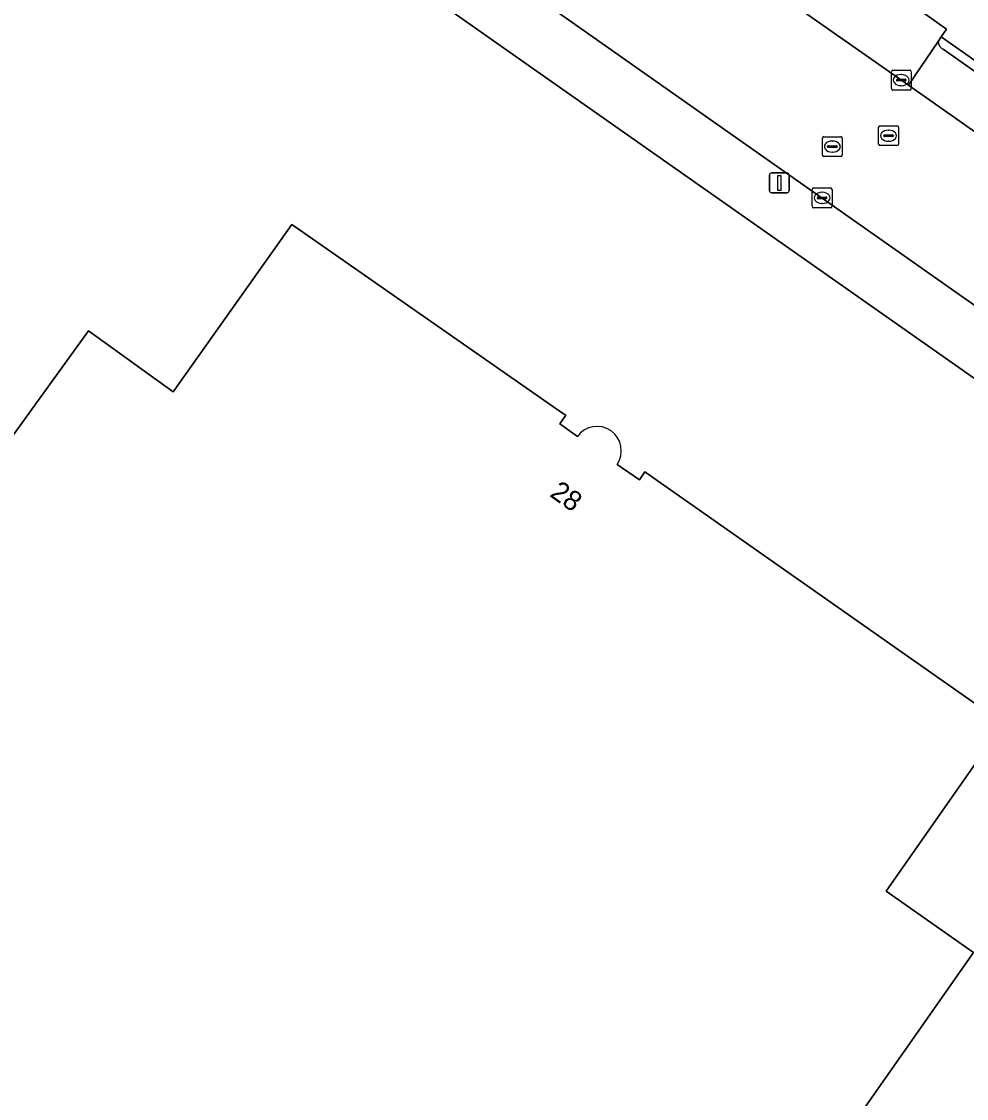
# Model space of a CAD drawing. Extents: x 155018 to 156648, y 383979 to 385733.
# Drawn here: x 155513.9 to 155561.5, y 384893 to 384947.3 of the extents above; entities that cross this region are included whole.
import ezdxf

# ---------------------------------------------------------------- set-up
doc = ezdxf.new("R2010")
doc.units = 0
for name, color, linetype in [('IMGEO_Erf', 7, 'Continuous'), ('IMGEO_Kolk', 7, 'Continuous'), ('IMGEO_Lichtmast', 7, 'Continuous'), ('IMGEO_Pand', 7, 'Continuous'), ('IMGEO_Pand_nummerreeks', 7, 'Continuous'), ('IMGEO_Parkeervlak_open', 7, 'Continuous'), ('IMGEO_Rijbaan_lokaal_gesloten', 7, 'Continuous'), ('IMGEO_Rioolput', 7, 'Continuous'), ('IMGEO_Voetpad_open', 7, 'Continuous')]:
    doc.layers.add(name, color=color, linetype=linetype)

msp = doc.modelspace()

# ---------------------------------------------------------------- linework, layer by layer
at = {"layer": 'IMGEO_Erf'}
for points in [[(155457.525, 385018.63), (155458.619, 385017.864), (155484.145, 385000), (155491.64, 384994.721), (155500, 384988.865), (155510.83, 384981.203), (155511.294, 384981.88), (155516.258, 384978.35), (155515.775, 384977.663), (155553.601, 384951.142), (155553.738, 384951.046), (155554.058, 384951.47), (155560.497, 384946.89), (155560.229, 384946.497), (155580.857, 384931.994), (155586.597, 384927.958), (155607.46, 384913.427), (155617.317, 384906.512), (155620.874, 384904.014), (155651.48, 384882.509)], [(155645.703, 384870.176), (155613.715, 384892.628), (155600.657, 384901.793), (155582.308, 384914.778), (155574.917, 384919.981), (155570.133, 384923.483), (155539.854, 384944.743), (155535.161, 384948.038), (155534.984, 384948.163), (155531.101, 384950.889), (155530.5, 384951.311), (155510.828, 384965.124), (155506.264, 384968.328), (155505.588, 384968.803), (155501.395, 384971.747), (155500, 384972.727), (155492.047, 384978.311), (155491.266, 384978.86), (155482.605, 384984.76), (155482.381, 384984.92), (155460.927, 385000), (155450.653, 385007.222)], [(155500, 384877.008), (155485.234, 384887.357), (155500, 384907.81), (155514.306, 384927.626), (155517.232, 384931.679), (155521.497, 384928.598), (155527.474, 384937.038), (155541.136, 384927.524), (155541.289, 384927.418), (155540.987, 384926.985), (155541.878, 384926.35)], [(155543.877, 384924.937), (155545.004, 384924.158), (155545.287, 384924.561), (155563.372, 384911.879), (155557.442, 384903.43), (155561.847, 384900.331), (155558.976, 384896.238), (155532.714, 384858.794), (155540.579, 384853.259), (155545.535, 384849.771), (155571.761, 384887.2), (155574.63, 384891.294), (155591.828, 384879.262), (155575.198, 384855.542), (155560.868, 384835.103), (155560.52, 384834.638), (155543.355, 384846.66), (155543.923, 384847.471), (155538.96, 384850.949), (155531.075, 384856.475), (155530.489, 384855.639), (155507.887, 384871.48), (155500, 384877.008)]]:
    msp.add_lwpolyline(points, dxfattribs=at)
msp.add_arc((155542.869, 384925.631), 1.224, 325.4515, 144.0391, dxfattribs=at)
at = {"layer": 'IMGEO_Kolk'}
for p, q in [((155557.784, 384944.814), (155558.636, 384944.814)), ((155557.709, 384943.888), (155557.709, 384944.74)), ((155557.968, 384944.308), (155557.968, 384944.32)), ((155558.406, 384944.271), (155558.008, 384944.271)), ((155558.011, 384944.357), (155558.409, 384944.357)), ((155558.197, 384944.594), (155558.222, 384944.594)), ((155558.452, 384944.32), (155558.452, 384944.308)), ((155558.71, 384944.74), (155558.71, 384943.888)), ((155558.636, 384943.814), (155557.784, 384943.814)), ((155558.22, 384944.034), (155558.195, 384944.034)), ((155553.716, 384937.952), (155553.716, 384938.804)), ((155553.791, 384938.878), (155554.643, 384938.878)), ((155554.717, 384938.804), (155554.717, 384937.952)), ((155553.975, 384938.372), (155553.975, 384938.384)), ((155554.413, 384938.335), (155554.015, 384938.335)), ((155554.018, 384938.421), (155554.416, 384938.421)), ((155554.204, 384938.658), (155554.229, 384938.658)), ((155554.459, 384938.384), (155554.459, 384938.372)), ((155554.643, 384937.878), (155553.791, 384937.878)), ((155554.227, 384938.098), (155554.202, 384938.098))]:
    msp.add_line(p, q, dxfattribs=at)
for points in [[(155557.784, 384944.814), (155558.636, 384944.814)], [(155557.709, 384943.888), (155557.709, 384944.74)], [(155558.71, 384944.74), (155558.71, 384943.888)], [(155558.636, 384943.814), (155557.784, 384943.814)], [(155553.716, 384937.952), (155553.716, 384938.804)], [(155553.791, 384938.878), (155554.643, 384938.878)], [(155554.717, 384938.804), (155554.717, 384937.952)], [(155554.643, 384937.878), (155553.791, 384937.878)]]:
    msp.add_lwpolyline(points, dxfattribs=at)
for centre, radius, start, end in [((155557.786, 384944.738), 0.0765, 91.552, 178.448), ((155557.786, 384944.738), 0.0765, 91.552, 178.448), ((155558.634, 384944.738), 0.0765, 1.552, 88.448), ((155558.634, 384944.738), 0.0765, 1.552, 88.448), ((155558.008, 384944.317), 0.0403, 85.8775, 175.7526), ((155558.005, 384944.307), 0.0366, 178.938, 274.7102), ((155558.409, 384944.314), 0.043, 264.8664, 352.4533), ((155558.413, 384944.319), 0.0386, 1.7309, 96.639), ((155557.786, 384943.89), 0.0765, 181.552, 268.448), ((155557.786, 384943.89), 0.0765, 181.552, 268.448), ((155558.634, 384943.89), 0.0765, 271.552, 358.448), ((155558.634, 384943.89), 0.0765, 271.552, 358.448), ((155553.793, 384938.802), 0.0765, 91.552, 178.448), ((155553.793, 384938.802), 0.0765, 91.552, 178.448), ((155554.641, 384938.802), 0.0765, 1.552, 88.448), ((155554.641, 384938.802), 0.0765, 1.552, 88.448), ((155554.015, 384938.381), 0.0403, 85.8775, 175.7526), ((155554.012, 384938.371), 0.0366, 178.938, 274.7102), ((155554.416, 384938.378), 0.043, 264.8664, 352.4533), ((155554.42, 384938.383), 0.0386, 1.7309, 96.639), ((155553.793, 384937.954), 0.0765, 181.552, 268.448), ((155553.793, 384937.954), 0.0765, 181.552, 268.448), ((155554.641, 384937.954), 0.0765, 271.552, 358.448), ((155554.641, 384937.954), 0.0765, 271.552, 358.448)]:
    msp.add_arc(centre, radius, start, end, dxfattribs=at)
for centre, major_axis, ratio, start_param, end_param in [((155558.196, 384944.314), (-0.387, 0.002), 0.722429, 4.712389, 7.853982), ((155558.221, 384944.314), (-0.39, 0.002), 0.717154, 1.570796, 4.712389), ((155554.203, 384938.378), (-0.387, 0.002), 0.722429, 4.712389, 7.853982), ((155554.228, 384938.378), (-0.39, 0.002), 0.717154, 1.570796, 4.712389)]:
    msp.add_ellipse(centre, major_axis=major_axis, ratio=ratio, start_param=start_param, end_param=end_param, dxfattribs=at)
at = {"layer": 'IMGEO_Lichtmast'}
for p, q in [((155551.565, 384938.732), (155551.565, 384939.532)), ((155551.565, 384939.532), (155551.565, 384938.732)), ((155551.665, 384939.632), (155552.455, 384939.632)), ((155552.455, 384939.632), (155551.665, 384939.632)), ((155552.555, 384939.532), (155552.555, 384938.732)), ((155552.555, 384938.732), (155552.555, 384939.532)), ((155552.455, 384938.632), (155551.665, 384938.632)), ((155551.665, 384938.632), (155552.455, 384938.632))]:
    msp.add_line(p, q, dxfattribs=at)
msp.add_lwpolyline([(155551.985, 384939.507), (155552.135, 384939.507), (155552.135, 384938.757), (155551.985, 384938.757), (155551.985, 384939.507)], dxfattribs=at)
for centre, start, end in [((155551.665, 384939.532), 90, 180), ((155551.665, 384939.532), 90, 180), ((155552.455, 384939.532), 0, 90), ((155552.455, 384939.532), 360, 90), ((155551.665, 384938.732), 180, 270), ((155551.665, 384938.732), 180, 270), ((155552.455, 384938.732), 270, 0), ((155552.455, 384938.732), 270, 0)]:
    msp.add_arc(centre, 0.1, start, end, dxfattribs=at)
at = {"layer": 'IMGEO_Pand'}
msp.add_lwpolyline([(155541.878, 384926.35), (155540.987, 384926.985), (155541.289, 384927.418), (155541.136, 384927.524), (155527.474, 384937.038), (155521.497, 384928.598), (155517.232, 384931.679), (155514.306, 384927.626), (155500, 384907.81), (155485.234, 384887.357), (155500, 384877.008), (155507.887, 384871.48), (155530.489, 384855.639), (155531.075, 384856.475), (155538.96, 384850.949), (155540.579, 384853.259), (155532.714, 384858.794), (155558.976, 384896.238), (155561.847, 384900.331), (155557.442, 384903.43), (155563.372, 384911.879), (155545.287, 384924.561), (155545.004, 384924.158), (155543.877, 384924.937)], dxfattribs=at)
msp.add_arc((155542.869, 384925.631), 1.224, 325.4515, 144.0391, dxfattribs=at)
at = {"layer": 'IMGEO_Parkeervlak_open'}
msp.add_lwpolyline([(155560.072, 384946.265), (155558.57, 384944.057), (155580.666, 384928.528), (155582.038, 384930.579), (155560.322, 384945.869)], dxfattribs=at)
msp.add_arc((155560.547, 384946.288), 0.476, 182.7926, 241.7369, dxfattribs=at)
at = {"layer": 'IMGEO_Rijbaan_lokaal_gesloten'}
for points in [[(155650.099, 384879.818), (155615.524, 384904.073), (155605.603, 384911.034), (155580.666, 384928.528), (155558.57, 384944.057), (155551.965, 384948.699), (155514.295, 384975.174), (155514.115, 384975.3), (155509.167, 384978.777), (155500, 384985.217), (155489.982, 384992.256), (155489.845, 384992.352), (155482.635, 384997.401), (155478.917, 385000), (155456.1, 385015.949)], [(155452.478, 385009.864), (155466.537, 385000), (155468.855, 384998.374), (155481.303, 384989.599), (155484.226, 384987.538), (155493.798, 384980.798), (155500, 384976.456), (155502.879, 384974.44), (155503.149, 384974.25), (155507.358, 384971.292), (155508.017, 384970.829), (155512.594, 384967.613), (155532.25, 384953.8), (155532.882, 384953.356), (155536.732, 384950.651), (155536.91, 384950.526), (155541.6, 384947.23), (155571.894, 384925.942), (155573.015, 384925.172), (155576.741, 384922.577), (155602.522, 384904.454), (155615.591, 384895.277), (155647.55, 384872.837)]]:
    msp.add_lwpolyline(points, dxfattribs=at)
at = {"layer": 'IMGEO_Rioolput'}
for p, q in [((155557.067, 384941.086), (155557.067, 384941.938)), ((155557.142, 384942.012), (155557.994, 384942.012)), ((155557.326, 384941.506), (155557.326, 384941.518)), ((155557.369, 384941.555), (155557.767, 384941.555)), ((155557.555, 384941.792), (155557.58, 384941.792)), ((155557.81, 384941.518), (155557.81, 384941.506)), ((155558.068, 384941.938), (155558.068, 384941.086)), ((155554.233, 384940.537), (155554.233, 384941.389)), ((155554.308, 384941.463), (155555.16, 384941.463)), ((155554.492, 384940.957), (155554.492, 384940.969)), ((155554.535, 384941.006), (155554.933, 384941.006)), ((155554.721, 384941.243), (155554.746, 384941.243)), ((155554.976, 384940.969), (155554.976, 384940.957)), ((155555.234, 384941.389), (155555.234, 384940.537)), ((155557.994, 384941.012), (155557.142, 384941.012)), ((155557.764, 384941.469), (155557.366, 384941.469)), ((155557.578, 384941.232), (155557.553, 384941.232)), ((155555.16, 384940.463), (155554.308, 384940.463)), ((155554.93, 384940.92), (155554.532, 384940.92)), ((155554.744, 384940.683), (155554.719, 384940.683))]:
    msp.add_line(p, q, dxfattribs=at)
for points in [[(155557.067, 384941.086), (155557.067, 384941.938)], [(155557.142, 384942.012), (155557.994, 384942.012)], [(155558.068, 384941.938), (155558.068, 384941.086)], [(155554.233, 384940.537), (155554.233, 384941.389)], [(155554.308, 384941.463), (155555.16, 384941.463)], [(155555.234, 384941.389), (155555.234, 384940.537)], [(155557.994, 384941.012), (155557.142, 384941.012)], [(155555.16, 384940.463), (155554.308, 384940.463)]]:
    msp.add_lwpolyline(points, dxfattribs=at)
for centre, radius, start, end in [((155557.144, 384941.936), 0.0765, 91.552, 178.448), ((155557.144, 384941.936), 0.0765, 91.552, 178.448), ((155557.366, 384941.515), 0.0403, 85.8775, 175.7526), ((155557.363, 384941.505), 0.0366, 178.938, 274.7102), ((155557.767, 384941.512), 0.043, 264.8664, 352.4533), ((155557.771, 384941.517), 0.0386, 1.7309, 96.639), ((155557.992, 384941.936), 0.0765, 1.552, 88.448), ((155557.992, 384941.936), 0.0765, 1.552, 88.448), ((155554.31, 384941.387), 0.0765, 91.552, 178.448), ((155554.31, 384941.387), 0.0765, 91.552, 178.448), ((155554.532, 384940.966), 0.0403, 85.8775, 175.7526), ((155554.529, 384940.956), 0.0366, 178.938, 274.7102), ((155554.933, 384940.963), 0.043, 264.8664, 352.4533), ((155554.937, 384940.968), 0.0386, 1.7309, 96.639), ((155555.158, 384941.387), 0.0765, 1.552, 88.448), ((155555.158, 384941.387), 0.0765, 1.552, 88.448), ((155557.144, 384941.088), 0.0765, 181.552, 268.448), ((155557.144, 384941.088), 0.0765, 181.552, 268.448), ((155557.992, 384941.088), 0.0765, 271.552, 358.448), ((155557.992, 384941.088), 0.0765, 271.552, 358.448), ((155554.31, 384940.539), 0.0765, 181.552, 268.448), ((155554.31, 384940.539), 0.0765, 181.552, 268.448), ((155555.158, 384940.539), 0.0765, 271.552, 358.448), ((155555.158, 384940.539), 0.0765, 271.552, 358.448)]:
    msp.add_arc(centre, radius, start, end, dxfattribs=at)
for centre, major_axis, ratio, start_param, end_param in [((155557.554, 384941.512), (-0.387, 0.002), 0.722429, 4.712389, 7.853982), ((155557.579, 384941.512), (-0.39, 0.002), 0.717154, 1.570796, 4.712389), ((155554.72, 384940.963), (-0.387, 0.002), 0.722429, 4.712389, 7.853982), ((155554.745, 384940.963), (-0.39, 0.002), 0.717154, 1.570796, 4.712389)]:
    msp.add_ellipse(centre, major_axis=major_axis, ratio=ratio, start_param=start_param, end_param=end_param, dxfattribs=at)
at = {"layer": 'IMGEO_Voetpad_open'}
for points in [[(155553.738, 384951.046), (155551.965, 384948.699), (155558.57, 384944.057), (155560.072, 384946.265), (155560.229, 384946.497), (155560.497, 384946.89), (155554.058, 384951.47)], [(155541.6, 384947.23), (155536.91, 384950.526), (155535.161, 384948.038), (155539.854, 384944.743), (155570.133, 384923.483), (155571.894, 384925.942)]]:
    msp.add_lwpolyline(points, close=True, dxfattribs=at)
for points in [[(155607.302, 384913.282), (155607.46, 384913.427), (155586.597, 384927.958), (155580.857, 384931.994), (155560.229, 384946.497), (155560.072, 384946.265)], [(155560.322, 384945.869), (155582.038, 384930.579), (155586.27, 384927.599), (155606.786, 384913.278)]]:
    msp.add_lwpolyline(points, dxfattribs=at)
msp.add_arc((155560.547, 384946.288), 0.476, 182.7926, 241.7369, dxfattribs=at)

# ---------------------------------------------------------------- texts
at = {"layer": 'IMGEO_Pand_nummerreeks'}
msp.add_text('28', height=1, rotation=324.8637, dxfattribs=at).set_placement((155540.437, 384923.361))

doc.saveas('drawing.dxf')
